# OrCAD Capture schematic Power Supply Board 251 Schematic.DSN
size A3; title: STCOMET PSU VIPER BOARD; rev: 251
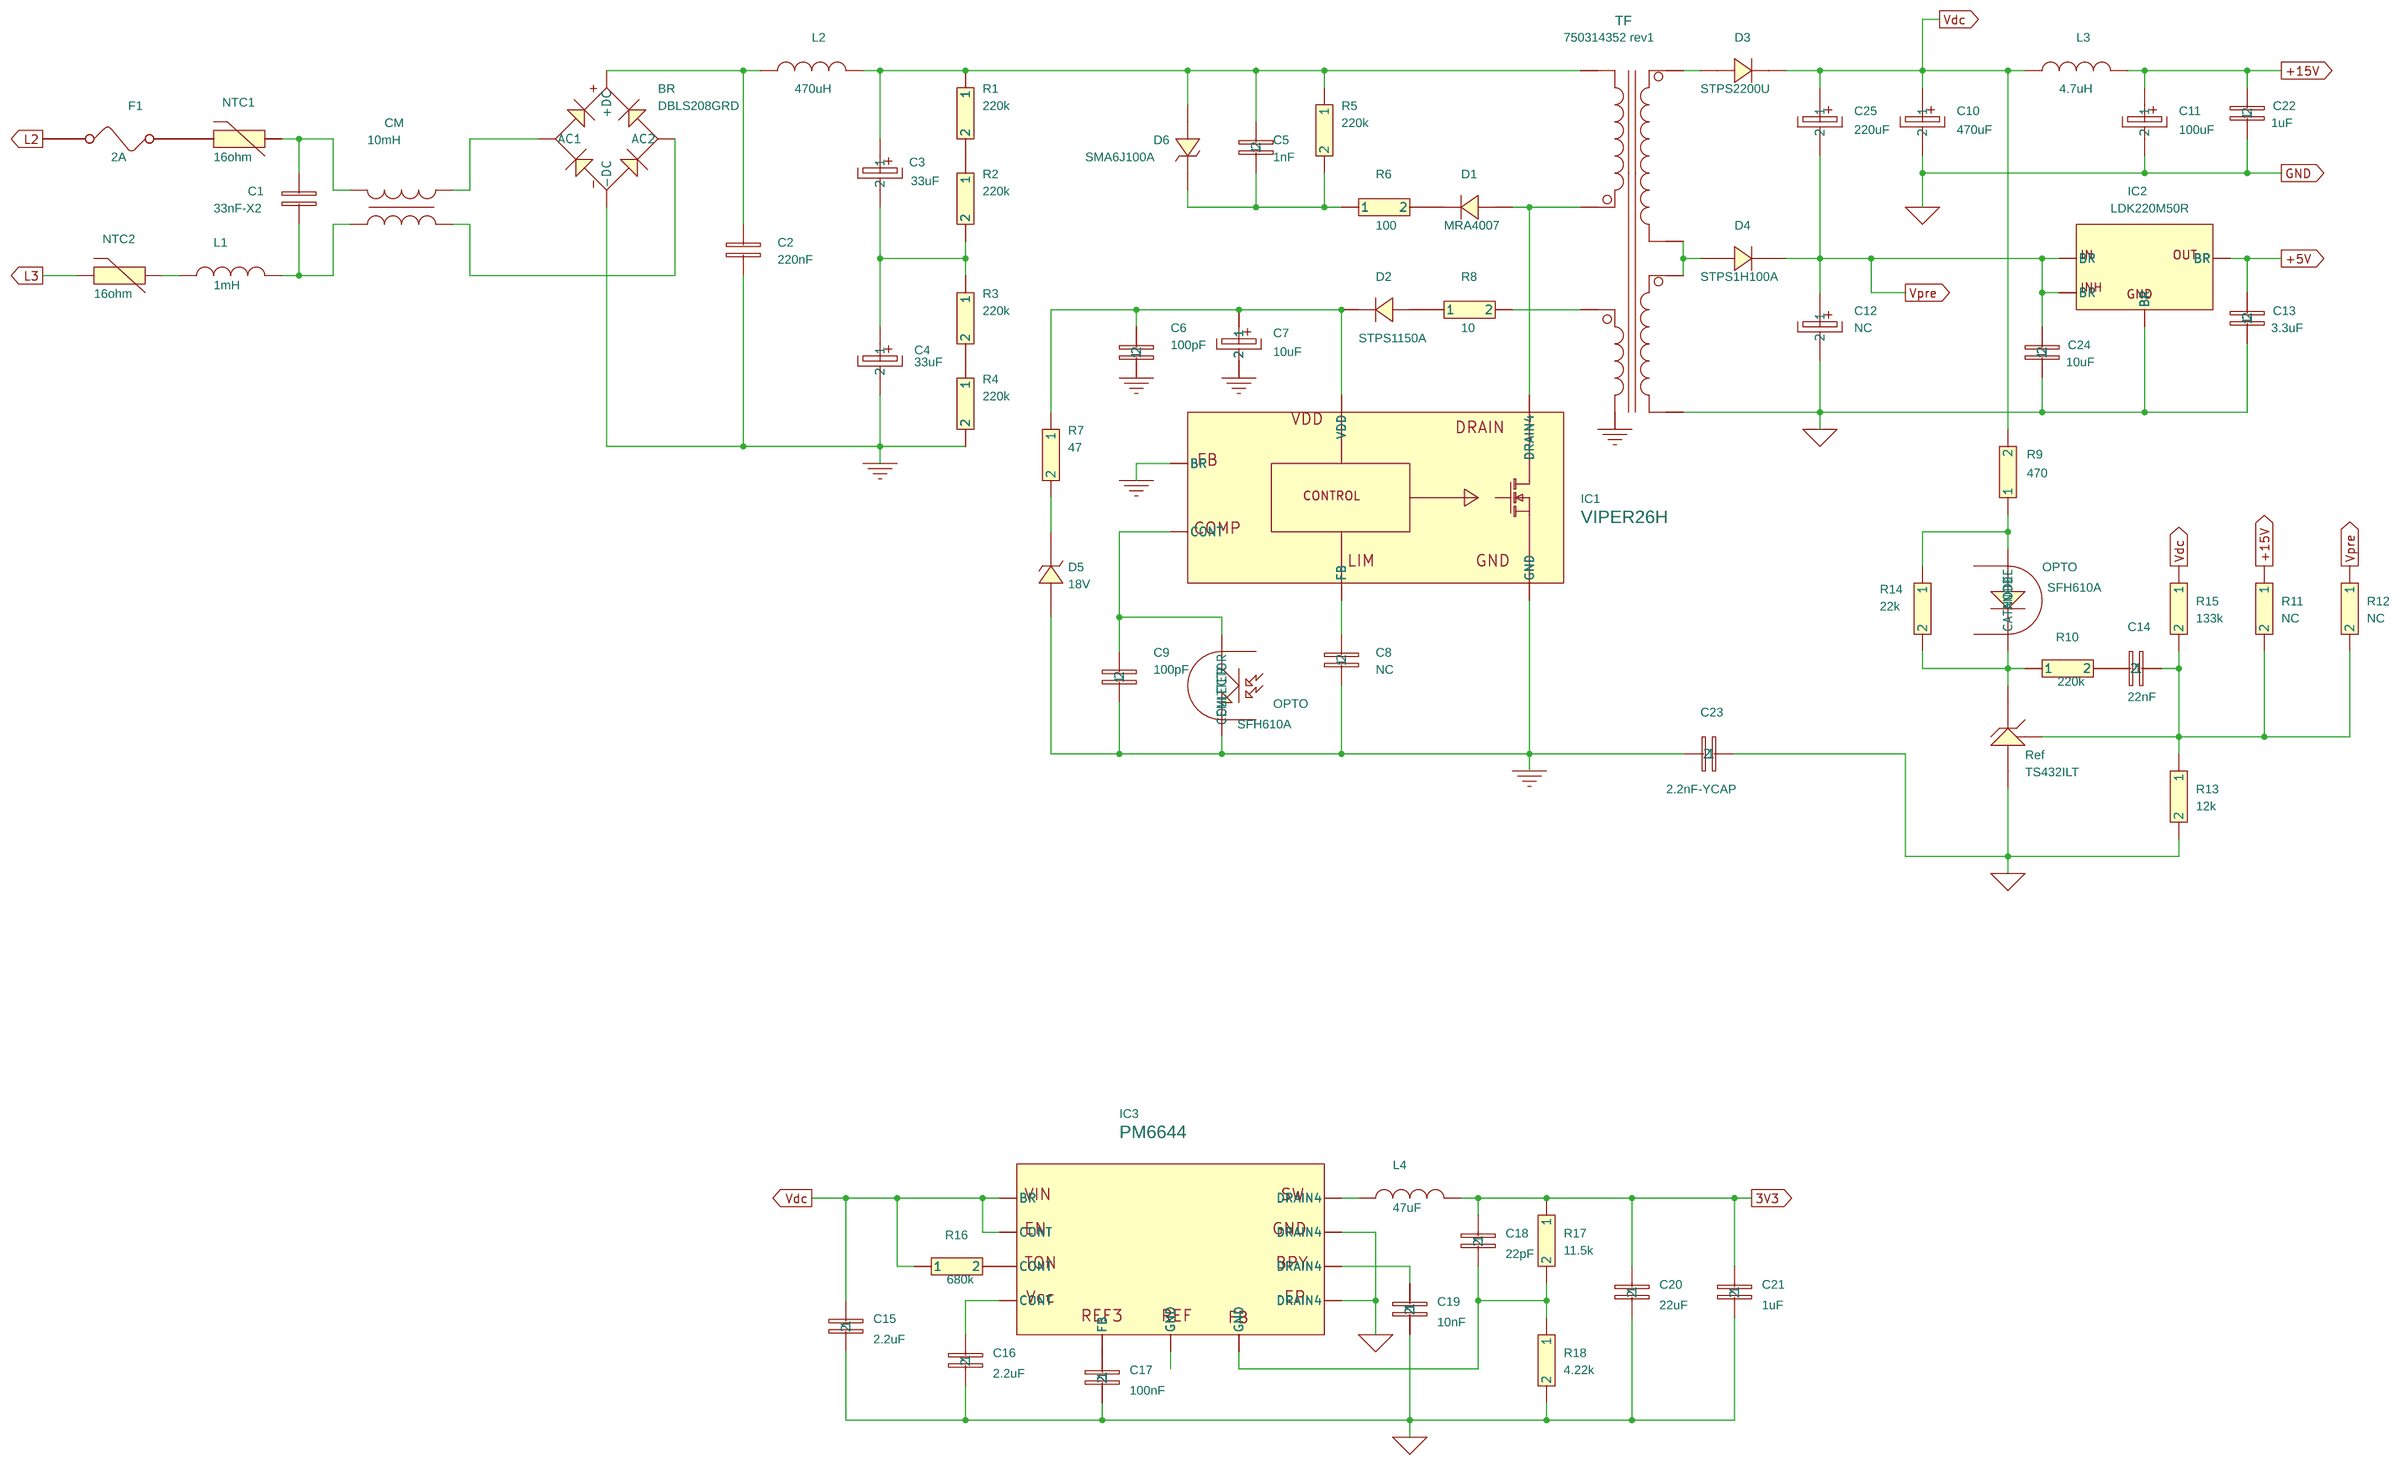
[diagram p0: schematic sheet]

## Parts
BR  DBLS208GRD  [DIP4/200]
C1  33nF-X2  [CAPC-2220]
C2  220nF  [CAPC-2220]
C3  33uF  [400V]
C4  33uF  [400V]
C5  1nF
C6  100pF
C7  10uF  [400V]
C8  NC
C9  100pF
C10  470uF  [400V]
C11  100uF  [400V]
C12  NC  [400V]
C13  3.3uF
C14  22nF
C15  2.2uF
C16  2.2uF
C17  100nF
C18  22pF
C19  10nF
C20  22uF
C21  1uF
C22  1uF
C23  2.2nF-YCAP
C24  10uF
C25  220uF  [400V]
CM  10mH  [IND-EPCOS-B82721K]
D1  MRA4007  [STTH1L06]
D2  STPS1150A  [STTH1L06]
D3  STPS2200U  [STTH1L06]
D4  STPS1H100A  [STTH1L06]
D5  18V
D6  SMA6J100A
F1  2A  [CYL/D.300/LS.200/.034]
IC1  VIPER26H  [SDIP 10L]
IC2  LDK220M50R  [SDIP 10L]
IC3  PM6644  [SDIP 10L]
L1  1mH  [INDC-EPCOS-B82462G4]
L2  470uH  [CYL/D.350/LS.200/.034]
L3  4.7uH  [CYL/D.350/LS.200/.034]
L4  47uF  [INDC-EPCOS-B82462G4]
NTC1  16ohm  [NTC-EPCOS-B57236]
NTC2  16ohm  [NTC-EPCOS-B57236]
OPTO  SFH610A
R1  220k  [1W]
R2  220k  [1W]
R3  220k  [1W]
R4  220k  [1W]
R5  220k  [1W]
R6  100  [1W]
R7  47  [1W]
R8  10  [1W]
R9  470  [1W]
R10  220k  [1W]
R11  NC  [1W]
R12  NC  [1W]
R13  12k  [1W]
R14  22k  [1W]
R15  133k  [1W]
R16  680k  [1W]
R17  11.5k  [1W]
R18  4.22k  [1W]
Ref  TS432ILT  [TO92]
TF  750314352 rev1  [TRAFO-TDK-SRW16ES]

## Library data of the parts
BR = BRIDGE_0
C1 C2 = CAP_0
C3 = CAPACITOR_POL_5
C4 = CAPACITOR_POL
C5 = CAP_8
C6 = CAP_6
C7 = CAPACITOR_POL_6
C8 = CAP_5
C9 = CAP_2
C10 = CAPACITOR_POL_2
C11 = CAPACITOR_POL_4
C12 = CAPACITOR_POL_1
C13 = CAP_13
C14 = CAP_14
C15 = CAP_7
C16 = CAP_1
C17 = CAP_11
C18 = CAP_9
C19 = CAP_15
C20 = CAP_10
C21 = CAP_3
C22 = CAP_12
C23 = CAP
C24 = CAP_4
C25 = CAPACITOR_POL_3
CM = INDUCTOR_IRON_1
D1-D4 = DIODE_0
D5 D6 = DIODE_ZENER1
F1 = FUSE
IC1 = VIPER37_SDIP10L_0_v2
IC2 = VIPER37_SDIP10L_4
IC3 = VIPER37_SDIP10L_3
L1 L4 = L
L2 L3 = INDUCTOR
NTC1 NTC2 R16 = R_3
OPTO = OPTO_ISOLATOR-A_3
R1 = R_11
R2 = R_10
R3 = R_17
R4 = R_9
R5 = R_13
R6 = R_7
R7 = R_14
R8 = R_4
R9 = R_2
R10 = R_12
R11 = R_6
R12 = R
R13 = R_15
R14 = R_5
R15 = R_1
R17 = R_16
R18 = R_8
Ref = TL431_0
TF = XFRM_NONLINEAR_6

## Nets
3V3: C18.1 C20.1 C21.1 L4.2 R17.1
+15V: C11.1 C22.2 L3.2 R11.1
GND_POWER: BR.-DC C2.1 C4.2 C6.1 C7.2 C8.1 C9.1 C23.2 D5.1(ANODE) IC1.BR IC1.GND OPTO.EMITTER R4.2 TF.7
GND_SIGNAL: C10.2 C11.2 C12.1 C12.2 C13.1 C13.2 C15.2 C16.2 C17.2 C19.1 C19.2 C20.2 C21.2 C22.1 C23.1 C24.1 C24.2 C25.2 D4.2(CATHODE) IC2.BR IC3.DRAIN4 L4.1 R12.1 R13.2 R18.2 Ref.2(A) TF.2
L2: F1.2
L3: NTC2.2
Vdc: C10.1 C15.1 C16.1 C25.1 D3.2(CATHODE) IC3.BR IC3.CONT L3.1 R9.2 R15.1 R16.1 R16.2
N1878154: C6.2 C7.1 D2.2(CATHODE) IC1.VDD R7.1
N1878208: C9.2 IC1.CONT OPTO.COLLECTOR
N1878276: C8.2 IC1.FB
N1878308: C3.1 C5.2 D6.1(ANODE) L2.2 R1.1 R5.1 TF.10
N1878376: BR.AC2 CM.1
N1878384: BR.+DC C2.2 L2.1
N1878412: BR.AC1 CM.2
N1878472: C1.2 CM.3 NTC1.1
N1878726: D4.1(ANODE) TF.3 TF.4
N1878976: C5.1 D6.2(CATHODE) R5.2 R6.1
N1879016: D1.1(ANODE) IC1.DRAIN4 TF.9
N2080964: C1.1 CM.4 L1.2
N2081029: L1.1 NTC2.1
N2082633: C3.2 C4.1 R2.2 R3.1
N2088324: R8.2 TF.8
N2089528: D3.1(ANODE) TF.5
N2091646: OPTO.CATHODE R10.1 R14.2 Ref.1(C)
N2091724: OPTO.ANODE R9.1 R14.1
N2091816: C14.1 R11.2 R12.2 R13.1 R15.2 Ref.3(VREF)
N2094181: D5.2(CATHODE) R7.2
N2115140: C18.2 IC3.GND R17.2 R18.1
N2121910: F1.1 NTC1.2
N2121915: R3.2 R4.1
N2121916: D1.2(CATHODE) R6.2
N2121917: R1.2 R2.1
N2123065: C17.1 IC3.FB
N2123945: C14.2 R10.2
N2128711: D2.1(ANODE) R8.1
